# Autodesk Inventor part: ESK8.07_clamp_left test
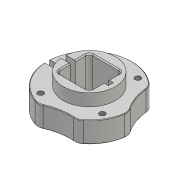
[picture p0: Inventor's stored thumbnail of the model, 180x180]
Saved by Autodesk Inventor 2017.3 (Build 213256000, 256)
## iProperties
Created: 2018-01
Part Number: ESK8.07_clamp_left test
Material: Aluminum 6061
Document SubType Name: Modeling
Designer: Tobias
Density: 2.7 g/cm^3
Appearance: Aluminum - Flat
Mass: 47.2161 g
Surface Area: 77.5268 cm^2
Volume: 17.4875 cm^3
Author: Tobias
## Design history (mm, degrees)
sketch "Sketch1"
  geometry: C1 r 24.5 at (0, 0); 1 further point
  constraints: 1 centre point, 1 coincident
  dimensions: "d0" = 49 diameter of C1
extrude "Extrusion1" new body sketch "Sketch1" stored distance "d1" = 12; taper "d2" = 0 deg
sketch "Sketch55"
  geometry: C1 r 15 at (0, 0); 1 further point
  constraints: 1 centre point, 1 coincident
  dimensions: "d386" = 30 diameter of C1
extrude "Extrusion36" join sketch "Sketch55" distance "d387" = 7; taper "d388" = 0 deg
sketch "Sketch56"
  geometry: L1 (-9.5, 9.5)-(9.5, 9.5); L2 (9.5, 9.5)-(9.5, -9.5); L3 (9.5, -9.5)-(-9.5, -9.5); L4 (-9.5, -9.5)-(-9.5, 9.5); L5 (0, 34.3)-(0, -34.3) reference; L6 (-34.3, 0)-(34.3, 0) reference; 1 further point
  constraints: 8 end point, 2 parallel, 2 perpendicular, 1 horizontal, 2 other
  dimensions: "d389" = 19 distance of L1.start L1.end
extrude "Extrusion37" cut sketch "Sketch56" stored distance "d390" = 14; taper "d391" = 0 deg
sketch "Sketch57"
  geometry: L1 (0, 34.3)-(0, -34.3) reference; L2 (-34.3, 0)-(34.3, 0) reference; L3 (-9.624, 18.1)-(0, 0); L4 (0, 0)-(10.25, 17.754); L5 (0, 0)-(-10.25, -17.754); L6 (0, 0)-(17.754, -10.25); A1 r 20.5 centre (0, 0) between (-9.624, 18.1) and (10.25, 17.754); 3 further points
  constraints: 8 end point, 4 coincident, 4 point on circle, 1 centre point
  dimensions: "d393" = 28 deg angle of L3 L1; "d394" = 41 diameter of A1; "d462" = 30 deg angle of L1 L4; "d512" = 30 deg angle of L1 L5; "d513" = 60 deg angle of L6 L1
hole "Hole13" sketch "Sketch57" at (-9.624, 18.1), (10.25, 17.754), (17.754, -10.25), (-10.25, -17.754) diameter "d395" = 3.242; stored, may be unused: countersink angle "d399" = 90 deg, drill point angle "d401" = 118 deg; dims "d396" = 8, "d397" = 4, "d398" = 2, "d400" = 11.8
workplane "Work Plane5"
workplane "Work Plane6"
sketch "Sketch66"
  geometry: L1 (20.363, 0)-(-34.675, 0) reference; L2 (-26.813, -1.5)-(-26.813, 1.5); L3 (-26.813, 1.5)-(12.5, 1.5); L4 (12.5, 1.5)-(12.5, -1.5); L5 (12.5, -1.5)-(-26.813, -1.5); L6 (0, 2.1)-(0, -2.1) reference
  constraints: 8 end point, 2 parallel, 1 perpendicular, 1 other
  dimensions: "d452" = 3 distance of L2.start L2.end; "d530" = 12.5 distance between parallel lines of L4 L6
extrude "Extrusion43" cut sketch "Sketch66" stored distance "d450" = 60; taper "d451" = 0 deg
workplane "Work Plane7"
sketch "Sketch68"
  geometry: L1 (12.95, 0)-(-12.95, 0) reference; L2 (0, 22.2)-(0, -3.7) reference; 2 further points
  constraints: 1 point on line
  dimensions: "d476" = 18.5 distance from line of point (0, 18.5) L1
hole "Hole15" sketch "Sketch68" at (0, 18.5) diameter "d464" = 5.5; stored, may be unused: countersink angle "d468" = 90 deg, drill point angle "d470" = 0 deg; dims "d465" = 6, "d466" = 10, "d467" = 17.75, "d469" = 57.25
sketch "Sketch71"
  geometry: L1 (6.51, 0)-(-6.51, 0) reference; L2 (0, 47.704)-(0, -7.951) reference; L3 (0, 18.5)-(0, 35.103); L4 (4.65, 18.5)-(4.65, 35.103); L5 (-4.65, 35.103)-(-4.65, 18.5); A1 r 4.65 centre (0, 18.5) between (-4.65, 18.5) and (4.65, 18.5); A2 r 4.65 centre (0, 35.103) between (4.65, 35.103) and (-4.65, 35.103); 2 further points
  constraints: 8 end point, 4 point on circle, 4 tangent, 2 centre point, 2 point on line, 1 midpoint, 1 parallel
  dimensions: "d477" = 9.3 distance between parallel lines of L5 L4; "d478" = 18.5 distance from line of L1 L3.start (derived)
extrude "Extrusion47" cut sketch "Sketch71" distance "d479" = 18; taper "d480" = 0 deg
sketch "Sketch72"
  geometry: L1 (0, -12.95)-(0, 12.95) reference; L2 (-3.7, 0)-(22.2, 0) reference; 2 further points
  constraints: 1 point on line
  dimensions: "d483" = 18.5 distance from line of point (18.5, 0) L1 (derived)
hole "Hole16" sketch "Sketch72" at (18.5, 0) diameter "d484" = 4.134; stored, may be unused: countersink angle "d488" = 90 deg, drill point angle "d490" = 118 deg; dims "d485" = 10, "d486" = 4, "d487" = 2, "d489" = 14.2
sketch "Sketch76"
  geometry: L1 (0, -39.291)-(0, 64.247) reference; L2 (-101.901, 0)-(45.567, 0) reference; L3 (0, 0)-(-49.334, 17.956); C1 r 31.5 at (-49.334, 17.956)
  constraints: 2 end point, 1 centre point
  dimensions: "d520" = 63 diameter of C1; "d521" = 52.5 distance of L3.start L3.end; "d522" = 20 deg angle of L2 L3
extrude "Extrusion51" cut sketch "Sketch76" stored distance "d514" = 7.75; taper "d515" = 0 deg
workplane "Work Plane8"
fillet "Fillet52" dims "d526" = 2
chamfer "Chamfer41" distance "d506" = 0.6; stored, may be unused: second distance "d507" = 2, angle "d508" = 45 deg
mirror "Mirror11"
fillet "Fillet51" dims "d516" = 6
chamfer "Chamfer44" distance "d535" = 0.3; stored, may be unused: second distance "d536" = 2, angle "d537" = 45 deg
body "Solid1"
other parameters: "d71" = 6, "d72" = 16, "d405" = 0, "d449" = -90 deg, "d463" = -25.5, "d533" = -30 deg
